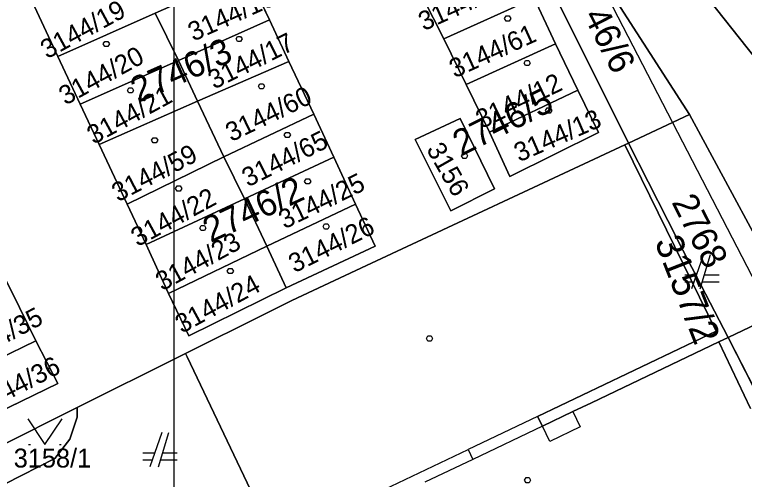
# Model space of a CAD drawing. Extents: x -263587 to -261993, y -1238795 to -1236748.
# Drawn here: x -263001.3 to -262958.9, y -1238463.81 to -1238436.79 of the extents above; entities that cross this region are included whole.
import ezdxf

# ---------------------------------------------------------------- set-up
doc = ezdxf.new("R2010")
doc.units = 0
for name, color, linetype in [('Vrstva 1', 7, 'Continuous'), ('Vrstva 3', 7, 'Continuous'), ('Vrstva 51', 7, 'Continuous')]:
    doc.layers.add(name, color=color, linetype=linetype)

msp = doc.modelspace()

# ---------------------------------------------------------------- linework, layer by layer
at = {"layer": 'Vrstva 1'}
for p, q in [((-262965.64, -1238444.26), (-262976.8, -1238421.88)), ((-262976.8, -1238421.88), (-262965.64, -1238444.26)), ((-262973.93, -1238422.08), (-262954.23, -1238460.19)), ((-262987.81, -1238434.35), (-262986.49, -1238437.1)), ((-262986.49, -1238437.1), (-262987.81, -1238434.35)), ((-262976.36, -1238438.21), (-262977.72, -1238435.51)), ((-262977.72, -1238435.51), (-262976.36, -1238438.21)), ((-262971.12, -1238435.83), (-262976.36, -1238438.21)), ((-262976.36, -1238438.21), (-262971.12, -1238435.83)), ((-262971.12, -1238435.83), (-262969.88, -1238438.49)), ((-262969.88, -1238438.49), (-262971.12, -1238435.83)), ((-262998.8, -1238439.23), (-263000.02, -1238436.62)), ((-263000.02, -1238436.62), (-262998.8, -1238439.23)), ((-262998.8, -1238439.23), (-262993.13, -1238436.72)), ((-262993.13, -1238436.72), (-262998.8, -1238439.23)), ((-262993.13, -1238436.72), (-262991.78, -1238439.46)), ((-262991.78, -1238439.46), (-262993.13, -1238436.72)), ((-262991.78, -1238439.46), (-262986.49, -1238437.1)), ((-262986.49, -1238437.1), (-262991.78, -1238439.46)), ((-262986.49, -1238437.1), (-262985.37, -1238439.52)), ((-262985.37, -1238439.52), (-262986.49, -1238437.1)), ((-262975.07, -1238440.85), (-262976.36, -1238438.21)), ((-262976.36, -1238438.21), (-262975.07, -1238440.85)), ((-262969.88, -1238438.49), (-262975.07, -1238440.85)), ((-262975.07, -1238440.85), (-262969.88, -1238438.49)), ((-262969.88, -1238438.49), (-262968.58, -1238441.19)), ((-262968.58, -1238441.19), (-262969.88, -1238438.49)), ((-262997.49, -1238442), (-262998.8, -1238439.23)), ((-262998.8, -1238439.23), (-262997.49, -1238442)), ((-262997.49, -1238442), (-262991.78, -1238439.46)), ((-262991.78, -1238439.46), (-262997.49, -1238442)), ((-262991.78, -1238439.46), (-262990.67, -1238441.83)), ((-262990.67, -1238441.83), (-262991.78, -1238439.46)), ((-262990.67, -1238441.83), (-262985.37, -1238439.52)), ((-262985.37, -1238439.52), (-262990.67, -1238441.83)), ((-262985.37, -1238439.52), (-262983.91, -1238442.58)), ((-262983.91, -1238442.58), (-262985.37, -1238439.52)), ((-262973.71, -1238443.62), (-262975.07, -1238440.85)), ((-262975.07, -1238440.85), (-262973.71, -1238443.62)), ((-262973.71, -1238443.62), (-262968.58, -1238441.19)), ((-262968.58, -1238441.19), (-262973.71, -1238443.62)), ((-262968.58, -1238441.19), (-262967.37, -1238443.64)), ((-262967.37, -1238443.64), (-262968.58, -1238441.19)), ((-262996.4, -1238444.35), (-262990.67, -1238441.83)), ((-262990.67, -1238441.83), (-262996.4, -1238444.35)), ((-262989.15, -1238445.06), (-262990.67, -1238441.83)), ((-262990.67, -1238441.83), (-262989.15, -1238445.06)), ((-262996.4, -1238444.35), (-262997.49, -1238442)), ((-262997.49, -1238442), (-262996.4, -1238444.35)), ((-262989.15, -1238445.06), (-262983.91, -1238442.58)), ((-262983.91, -1238442.58), (-262989.15, -1238445.06)), ((-262983.91, -1238442.58), (-262982.75, -1238445.08)), ((-262982.75, -1238445.08), (-262983.91, -1238442.58)), ((-262978.03, -1238444.06), (-262975.41, -1238442.84)), ((-262975.41, -1238442.84), (-262978.03, -1238444.06)), ((-262975.41, -1238442.84), (-262973.42, -1238446.92)), ((-262973.42, -1238446.92), (-262975.41, -1238442.84)), ((-262972.53, -1238446.2), (-262973.71, -1238443.62)), ((-262973.71, -1238443.62), (-262972.53, -1238446.2)), ((-262967.37, -1238443.64), (-262972.53, -1238446.2)), ((-262972.53, -1238446.2), (-262967.37, -1238443.64)), ((-262994.77, -1238447.81), (-262996.4, -1238444.35)), ((-262996.4, -1238444.35), (-262994.77, -1238447.81)), ((-262965.85, -1238444.36), (-262980.85, -1238451.37)), ((-262980.85, -1238451.37), (-262965.85, -1238444.36)), ((-262975.95, -1238448.21), (-262978.03, -1238444.06)), ((-262978.03, -1238444.06), (-262975.95, -1238448.21)), ((-262965.64, -1238444.26), (-262965.85, -1238444.36)), ((-262965.85, -1238444.36), (-262965.64, -1238444.26)), ((-262960.55, -1238455.19), (-262965.85, -1238444.36)), ((-262965.85, -1238444.36), (-262960.55, -1238455.19)), ((-262963.34, -1238448.77), (-262965.64, -1238444.26)), ((-262965.64, -1238444.26), (-262963.34, -1238448.77)), ((-262989.15, -1238445.06), (-262994.77, -1238447.81)), ((-262994.77, -1238447.81), (-262989.15, -1238445.06)), ((-262987.95, -1238447.5), (-262989.15, -1238445.06)), ((-262989.15, -1238445.06), (-262987.95, -1238447.5)), ((-262982.75, -1238445.08), (-262987.95, -1238447.5)), ((-262987.95, -1238447.5), (-262982.75, -1238445.08)), ((-262982.75, -1238445.08), (-262981.49, -1238447.82)), ((-262981.49, -1238447.82), (-262982.75, -1238445.08)), ((-262973.42, -1238446.92), (-262975.95, -1238448.21)), ((-262975.95, -1238448.21), (-262973.42, -1238446.92)), ((-262993.66, -1238450.16), (-262994.77, -1238447.81)), ((-262994.77, -1238447.81), (-262993.66, -1238450.16)), ((-262993.66, -1238450.16), (-262987.95, -1238447.5)), ((-262987.95, -1238447.5), (-262993.66, -1238450.16)), ((-262986.65, -1238450.26), (-262987.95, -1238447.5)), ((-262987.95, -1238447.5), (-262986.65, -1238450.26)), ((-262986.65, -1238450.26), (-262981.49, -1238447.82)), ((-262981.49, -1238447.82), (-262986.65, -1238450.26)), ((-262981.49, -1238447.82), (-262980.36, -1238450.26)), ((-262980.36, -1238450.26), (-262981.49, -1238447.82)), ((-262962.48, -1238450.48), (-262963.34, -1238448.77)), ((-262963.34, -1238448.77), (-262962.48, -1238450.48)), ((-262992.36, -1238453), (-262993.66, -1238450.16)), ((-262993.66, -1238450.16), (-262992.36, -1238453)), ((-262992.36, -1238453), (-262986.65, -1238450.26)), ((-262986.65, -1238450.26), (-262992.36, -1238453)), ((-262985.52, -1238452.67), (-262986.65, -1238450.26)), ((-262986.65, -1238450.26), (-262985.52, -1238452.67)), ((-262980.36, -1238450.26), (-262985.52, -1238452.67)), ((-262985.52, -1238452.67), (-262980.36, -1238450.26)), ((-262959.85, -1238455.57), (-262962.48, -1238450.48)), ((-262962.48, -1238450.48), (-262959.85, -1238455.57)), ((-262961.27, -1238450.73), (-262961.97, -1238452.73)), ((-262961.47, -1238452.73), (-262960.87, -1238450.73)), ((-262980.86, -1238451.37), (-262985.2, -1238453.41)), ((-262985.2, -1238453.41), (-262980.86, -1238451.37)), ((-262980.85, -1238451.37), (-262980.86, -1238451.37)), ((-262980.86, -1238451.37), (-262980.85, -1238451.37)), ((-262961.69, -1238451.93), (-262962.37, -1238451.93)), ((-262960.37, -1238451.93), (-262961.23, -1238451.93)), ((-262962.37, -1238452.33), (-262961.83, -1238452.33)), ((-262961.35, -1238452.33), (-262960.37, -1238452.33)), ((-263001.49, -1238452.87), (-263000.07, -1238455.75)), ((-263000.07, -1238455.75), (-263001.49, -1238452.87)), ((-262985.52, -1238452.67), (-262991.19, -1238455.47)), ((-262991.19, -1238455.47), (-262985.52, -1238452.67)), ((-262991.19, -1238455.47), (-262992.36, -1238453)), ((-262992.36, -1238453), (-262991.19, -1238455.47)), ((-262985.2, -1238453.41), (-262986.78, -1238454.2)), ((-262986.78, -1238454.2), (-262985.2, -1238453.41)), ((-262986.78, -1238454.2), (-262991.38, -1238456.5)), ((-262991.38, -1238456.5), (-262986.78, -1238454.2)), ((-262970.92, -1238460.15), (-262960.55, -1238455.19)), ((-262960.55, -1238455.19), (-262970.92, -1238460.15)), ((-263005.25, -1238458.26), (-263000.07, -1238455.75)), ((-263000.07, -1238455.75), (-263005.25, -1238458.26)), ((-263000.07, -1238455.75), (-262998.8, -1238458.23)), ((-262998.8, -1238458.23), (-263000.07, -1238455.75)), ((-262960.38, -1238455.82), (-262967.78, -1238459.35)), ((-262967.78, -1238459.35), (-262960.38, -1238455.82)), ((-262960.38, -1238455.82), (-262959.85, -1238455.57)), ((-262959.85, -1238455.57), (-262960.38, -1238455.82)), ((-262958.54, -1238459.69), (-262960.38, -1238455.82)), ((-262960.38, -1238455.82), (-262958.54, -1238459.69)), ((-262957.3, -1238460.54), (-262959.85, -1238455.57)), ((-262959.85, -1238455.57), (-262957.3, -1238460.54)), ((-262991.69, -1238456.65), (-262997.67, -1238459.64)), ((-262997.67, -1238459.64), (-262991.69, -1238456.65)), ((-262991.57, -1238456.59), (-262991.69, -1238456.65)), ((-262991.69, -1238456.65), (-262991.57, -1238456.59)), ((-262991.38, -1238456.5), (-262991.57, -1238456.59)), ((-262991.57, -1238456.59), (-262991.38, -1238456.5)), ((-262991.38, -1238456.5), (-262991.28, -1238456.69)), ((-262991.28, -1238456.69), (-262991.38, -1238456.5)), ((-262991.28, -1238456.69), (-262986.16, -1238467.43)), ((-262986.16, -1238467.43), (-262991.28, -1238456.69)), ((-262998.8, -1238458.23), (-263003.83, -1238460.68)), ((-263003.83, -1238460.68), (-262998.8, -1238458.23)), ((-263002.94, -1238462.27), (-262997.67, -1238459.64)), ((-262997.67, -1238459.64), (-263002.94, -1238462.27)), ((-262997.67, -1238459.64), (-262997.67, -1238460.19)), ((-262997.67, -1238460.19), (-262997.67, -1238459.64)), ((-262967.78, -1238459.35), (-262968.87, -1238459.87)), ((-262968.87, -1238459.87), (-262967.78, -1238459.35)), ((-262970.92, -1238460.15), (-262974.95, -1238462.07)), ((-262970.64, -1238460.72), (-262970.92, -1238460.15)), ((-262970.92, -1238460.15), (-262970.64, -1238460.72)), ((-262968.87, -1238459.87), (-262970.64, -1238460.72)), ((-262970.64, -1238460.72), (-262968.87, -1238459.87)), ((-262968.87, -1238459.87), (-262968.44, -1238460.76)), ((-262997.67, -1238460.19), (-262998.09, -1238461.48)), ((-262998.09, -1238461.48), (-262997.67, -1238460.19)), ((-262970.64, -1238460.72), (-262974.68, -1238462.65)), ((-262970.21, -1238461.61), (-262970.64, -1238460.72)), ((-262968.44, -1238460.76), (-262970.21, -1238461.61)), ((-262992.75, -1238461.08), (-262993.45, -1238463.08)), ((-262992.95, -1238463.08), (-262992.35, -1238461.08)), ((-263000.49, -1238461.78), (-263000.39, -1238461.78)), ((-262998.09, -1238461.48), (-262998.96, -1238462.59)), ((-262998.96, -1238462.59), (-262998.09, -1238461.48)), ((-262998.69, -1238461.78), (-262998.59, -1238461.78)), ((-262993.17, -1238462.28), (-262993.85, -1238462.28)), ((-262991.85, -1238462.28), (-262992.71, -1238462.28)), ((-262980.24, -1238464.59), (-262974.95, -1238462.07)), ((-262974.95, -1238462.07), (-262974.68, -1238462.65)), ((-262998.96, -1238462.59), (-263001.85, -1238464.06)), ((-263001.85, -1238464.06), (-262998.96, -1238462.59)), ((-262993.85, -1238462.68), (-262993.31, -1238462.68)), ((-262992.83, -1238462.68), (-262991.85, -1238462.68)), ((-262974.68, -1238462.65), (-262977.47, -1238463.98))]:
    msp.add_line(p, q, dxfattribs=at)
for points in [[(-262972.56, -1238436.87), (-262972.47, -1238437.02), (-262972.56, -1238437.17), (-262972.74, -1238437.17), (-262972.83, -1238437.02), (-262972.74, -1238436.87)], [(-262988.17, -1238438.06), (-262988.08, -1238438.21), (-262988.17, -1238438.36), (-262988.35, -1238438.36), (-262988.44, -1238438.21), (-262988.35, -1238438.06)], [(-262995.88, -1238438.35), (-262995.79, -1238438.5), (-262995.88, -1238438.65), (-262996.06, -1238438.65), (-262996.15, -1238438.5), (-262996.06, -1238438.35)], [(-262971.43, -1238439.46), (-262971.34, -1238439.61), (-262971.43, -1238439.76), (-262971.61, -1238439.76), (-262971.7, -1238439.61), (-262971.61, -1238439.46)], [(-262994.48, -1238441.05), (-262994.39, -1238441.2), (-262994.48, -1238441.35), (-262994.66, -1238441.35), (-262994.75, -1238441.2), (-262994.66, -1238441.05)], [(-262986.87, -1238440.81), (-262986.78, -1238440.96), (-262986.87, -1238441.11), (-262987.05, -1238441.11), (-262987.14, -1238440.96), (-262987.05, -1238440.81)], [(-262970.18, -1238442.22), (-262970.09, -1238442.37), (-262970.18, -1238442.52), (-262970.36, -1238442.52), (-262970.45, -1238442.37), (-262970.36, -1238442.22)], [(-262993.08, -1238443.95), (-262992.99, -1238444.1), (-262993.08, -1238444.25), (-262993.26, -1238444.25), (-262993.35, -1238444.1), (-262993.26, -1238443.95)], [(-262985.37, -1238443.64), (-262985.28, -1238443.79), (-262985.37, -1238443.94), (-262985.55, -1238443.94), (-262985.64, -1238443.79), (-262985.55, -1238443.64)], [(-262975.07, -1238444.85), (-262974.98, -1238445), (-262975.07, -1238445.15), (-262975.25, -1238445.15), (-262975.34, -1238445), (-262975.25, -1238444.85)], [(-262984.19, -1238446.34), (-262984.1, -1238446.49), (-262984.19, -1238446.64), (-262984.37, -1238446.64), (-262984.46, -1238446.49), (-262984.37, -1238446.34)], [(-262991.68, -1238446.75), (-262991.59, -1238446.9), (-262991.68, -1238447.05), (-262991.86, -1238447.05), (-262991.95, -1238446.9), (-262991.86, -1238446.75)], [(-262990.28, -1238449.05), (-262990.19, -1238449.2), (-262990.28, -1238449.35), (-262990.46, -1238449.35), (-262990.55, -1238449.2), (-262990.46, -1238449.05)], [(-262983.11, -1238448.96), (-262983.02, -1238449.11), (-262983.11, -1238449.26), (-262983.29, -1238449.26), (-262983.38, -1238449.11), (-262983.29, -1238448.96)], [(-262988.68, -1238451.55), (-262988.59, -1238451.7), (-262988.68, -1238451.85), (-262988.86, -1238451.85), (-262988.95, -1238451.7), (-262988.86, -1238451.55)], [(-262977.11, -1238455.47), (-262977.02, -1238455.62), (-262977.11, -1238455.77), (-262977.29, -1238455.77), (-262977.38, -1238455.62), (-262977.29, -1238455.47)], [(-262971.41, -1238463.7), (-262971.32, -1238463.85), (-262971.41, -1238464), (-262971.59, -1238464), (-262971.68, -1238463.85), (-262971.59, -1238463.7)]]:
    msp.add_lwpolyline(points, close=True, dxfattribs=at)
msp.add_lwpolyline([(-263000.54, -1238460.28), (-262999.54, -1238461.78), (-262998.54, -1238460.28)], dxfattribs=at)
at = {"layer": 'Vrstva 3'}
for points in [[(-262994.91, -1238373.67), (-262989.53, -1238382.87), (-262982.03, -1238395.82), (-262973.48, -1238410.07), (-262972.59, -1238411.61), (-262957.85, -1238431.45), (-262958.52, -1238431.77), (-262956.45, -1238435.844), (-262953.39, -1238445.46), (-262964.97, -1238430.84), (-262975.87, -1238413.45), (-262976.83, -1238411.84), (-262987.85, -1238393.55), (-262998.59, -1238375.67), (-262999.53, -1238373.93)], [(-262975.87, -1238413.45), (-262964.97, -1238430.84), (-262953.39, -1238445.46), (-262941.84, -1238464.14), (-262938.08, -1238472.48), (-262924.76, -1238500.02), (-262923.643, -1238502.49), (-262927, -1238497.61), (-262938.23, -1238482.69), (-262940.64, -1238479.43), (-262947.17, -1238470.61), (-262951.06, -1238463.74), (-262956.07, -1238453.77), (-262962.09, -1238442.6), (-262971.05, -1238428.67), (-262972.2, -1238427.04), (-262974.28, -1238423.68), (-262976.8, -1238421.88), (-262977.77, -1238419.82), (-262978.15, -1238418.98)]]:
    msp.add_lwpolyline(points, dxfattribs=at)
for points in [[(-262962.09, -1238442.6), (-262965.64, -1238444.26), (-262973.856, -1238427.783), (-262972.2, -1238427.04), (-262971.05, -1238428.67)], [(-262990.67, -1238441.83), (-262985.37, -1238439.52), (-262986.49, -1238437.1), (-262987.81, -1238434.35), (-262989.09, -1238431.69), (-262990.18, -1238429.37), (-262995.49, -1238431.89), (-263000.98, -1238434.56), (-263000.02, -1238436.62), (-262998.8, -1238439.23), (-262997.49, -1238442), (-262996.4, -1238444.35)], [(-262990.18, -1238429.37), (-262989.09, -1238431.69), (-262987.81, -1238434.35), (-262993.13, -1238436.72), (-262998.8, -1238439.23), (-263000.02, -1238436.62), (-263000.98, -1238434.56), (-262995.49, -1238431.89)], [(-262987.81, -1238434.35), (-262986.49, -1238437.1), (-262985.37, -1238439.52), (-262990.67, -1238441.83), (-262996.4, -1238444.35), (-262997.49, -1238442), (-262998.8, -1238439.23), (-262993.13, -1238436.72)], [(-262967.37, -1238443.64), (-262968.58, -1238441.19), (-262969.88, -1238438.49), (-262975.07, -1238440.85), (-262973.71, -1238443.62), (-262972.53, -1238446.2)], [(-262969.88, -1238438.49), (-262968.58, -1238441.19), (-262967.37, -1238443.64), (-262972.53, -1238446.2), (-262973.71, -1238443.62), (-262975.07, -1238440.85)], [(-262962.09, -1238442.6), (-262956.07, -1238453.77), (-262959.85, -1238455.57), (-262962.48, -1238450.48), (-262963.341, -1238448.77), (-262965.64, -1238444.26)], [(-263003.83, -1238460.68), (-262998.8, -1238458.23), (-263000.07, -1238455.75), (-263001.49, -1238452.87), (-263002.93, -1238450.08), (-263004.12, -1238447.49), (-263005.59, -1238444.59), (-263011.13, -1238447.32), (-263016.85, -1238450.11), (-263015.33, -1238453.11), (-263013.98, -1238455.73), (-263012.56, -1238458.46), (-263011.16, -1238461.2), (-263009.85, -1238463.75), (-263009.05, -1238463.3)], [(-263005.59, -1238444.59), (-263004.12, -1238447.49), (-263002.93, -1238450.08), (-263001.49, -1238452.87), (-263000.07, -1238455.75), (-262998.8, -1238458.23), (-263003.83, -1238460.68), (-263009.05, -1238463.3), (-263009.85, -1238463.75), (-263011.16, -1238461.2), (-263012.56, -1238458.46), (-263013.98, -1238455.73), (-263015.33, -1238453.11), (-263016.85, -1238450.11), (-263011.13, -1238447.32)], [(-262985.52, -1238452.67), (-262980.36, -1238450.26), (-262981.49, -1238447.82), (-262982.75, -1238445.08), (-262987.95, -1238447.5), (-262989.15, -1238445.06), (-262994.77, -1238447.81), (-262993.66, -1238450.16), (-262992.36, -1238453), (-262991.19, -1238455.47)], [(-262982.75, -1238445.08), (-262981.49, -1238447.82), (-262980.36, -1238450.26), (-262985.52, -1238452.67), (-262991.19, -1238455.47), (-262992.36, -1238453), (-262993.66, -1238450.16), (-262994.77, -1238447.81), (-262989.15, -1238445.06), (-262987.95, -1238447.5)], [(-262951.06, -1238463.74), (-262947.17, -1238470.61), (-262951.58, -1238472.83), (-262953.1, -1238469.57), (-262953.6, -1238468.49), (-262957.3, -1238460.54), (-262959.85, -1238455.57), (-262956.07, -1238453.77)]]:
    msp.add_lwpolyline(points, close=True, dxfattribs=at)
at = {"layer": 'Vrstva 51'}
msp.add_lwpolyline([(-262992.03, -1237088.09), (-262695.03, -1237088.09), (-262695.03, -1238768.09), (-262992.03, -1238768.09)], close=True, dxfattribs=at)

# ---------------------------------------------------------------- texts
at = {"layer": 'Vrstva 1'}
for s, height, rotation, p in [('3144/62', 1.1, 24.2934, (-262977.528, -1238437.763)), ('3144/16', 1.1, 24.1788, (-262990.918, -1238438.371)), ('3144/19', 1.1, 28.5333, (-262999.419, -1238439.397)), ('3144/61', 1.1, 24.408, (-262975.735, -1238440.504)), ('3144/17', 1.1, 26.5279, (-262989.712, -1238441.159)), ('3144/20', 1.1, 28.5333, (-262998.351, -1238442.087)), ('3144/12', 1.1, 25.7831, (-262974.171, -1238443.454)), ('3144/21', 1.1, 28.5333, (-262996.715, -1238444.372)), ('3144/60', 1.1, 25.7831, (-262988.712, -1238444.213)), ('3144/13', 1.1, 23.5486, (-262971.984, -1238445.386)), ('3144/65', 1.1, 26.5279, (-262987.749, -1238446.842)), ('3144/59', 1.1, 27.5593, (-262995.293, -1238447.71)), ('3156', 1.1, 299.7142, (-262977.405, -1238444.623)), ('3144/25', 1.1, 26.0696, (-262985.62, -1238449.281)), ('3144/22', 1.1, 28.5333, (-262994.159, -1238450.314)), ('3144/26', 1.1, 26.5279, (-262985.039, -1238451.832)), ('3144/23', 1.1, 28.5333, (-262992.729, -1238452.884)), ('3157/2', 1.6, 291.349, (-262964.132, -1238449.994)), ('3144/24', 1.1, 28.5333, (-262991.589, -1238455.354)), ('3144/35', 1.1, 27.6166, (-263004.267, -1238457.19)), ('3144/36', 1.1, 27.2155, (-263003.27, -1238460.009))]:
    msp.add_text(s, height=height, rotation=rotation, dxfattribs=at).set_placement(p)
msp.add_text('3158/1', height=1.1, dxfattribs=at).set_placement((-263001.356, -1238463.12))
at = {"layer": 'Vrstva 3'}
for s, rotation, p in [('2746/6', 297.0213, (-262969.288, -1238434.877)), ('2746/3', 23.9496, (-262994.135, -1238441.944)), ('2746/5', 26.5852, (-262975.361, -1238445.05)), ('2746/2', 24.8664, (-262989.917, -1238450.074)), ('2768', 297.0213, (-262963.155, -1238447.697))]:
    msp.add_text(s, height=1.5, rotation=rotation, dxfattribs=at).set_placement(p)

doc.saveas('drawing.dxf')
